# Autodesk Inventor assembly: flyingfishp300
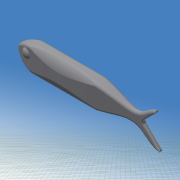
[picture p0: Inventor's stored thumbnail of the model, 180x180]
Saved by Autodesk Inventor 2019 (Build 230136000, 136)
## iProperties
Created: 2021-05
Part Number: flyingfishp300
Material: 一般
Document SubType Name: Assembly
Designer: kikut
Author: kikut
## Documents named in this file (2)
- F:\openFOAM\flyingfish\flyingfish15\oversetmesh\CAD\flyingfishp300.iam
- F:\openFOAM\flyingfish\flyingfish15\oversetmesh\CAD\flyingfish.ipt
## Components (1 placed, 1 different names)
1. flyingfish:1 — フラッシュ:1
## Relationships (1: Flush 1)
- フラッシュ:1 [Flush]: flyingfish:1
